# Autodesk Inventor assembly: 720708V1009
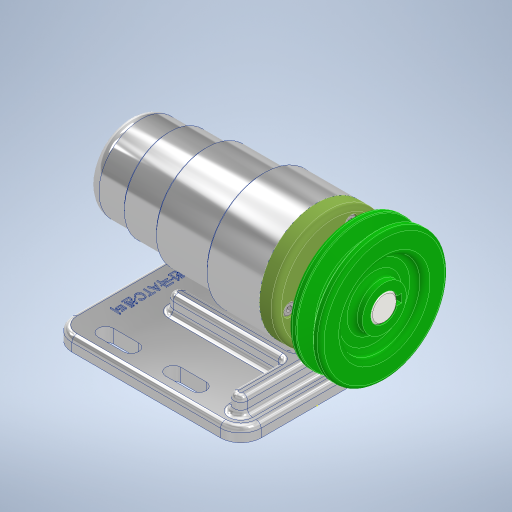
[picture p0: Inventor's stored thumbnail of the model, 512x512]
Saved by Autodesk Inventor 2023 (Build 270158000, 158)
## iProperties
Created: 2022-07
Part Number: 720708V1009
Document SubType Name: Assembly
Designer: owner
Author: owner
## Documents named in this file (12)
- C:\Users\owner\Desktop\720708V1009\720708V1009.iam
- C:\Users\owner\Desktop\720708V1009\본체.ipt
- C:\Users\owner\Desktop\720708V1009\V벨트풀리.ipt
- C:\Users\owner\Desktop\720708V1009\멈춤나사 M3.ipt
- C:\Users\owner\Desktop\720708V1009\베어링 6004.ipt
- C:\Users\owner\Desktop\720708V1009\베어링 51202.ipt
- C:\Users\owner\Desktop\720708V1009\볼트 M4.ipt
- C:\Users\owner\Desktop\720708V1009\어댑터슬리브.ipt
- C:\Users\owner\Desktop\720708V1009\오일 실 20x35x7.ipt
- C:\Users\owner\Desktop\720708V1009\축.ipt
- C:\Users\owner\Desktop\720708V1009\커버.ipt
- C:\Users\owner\Desktop\720708V1009\키 5x5.ipt
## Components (1 placed, 1 different names)
1. V벨트풀리:1 — 강체:8, 강체:9
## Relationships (2: WeldJoint 2)
- 강체:8 [WeldJoint]: V벨트풀리:1
- 강체:9 [WeldJoint]: V벨트풀리:1
